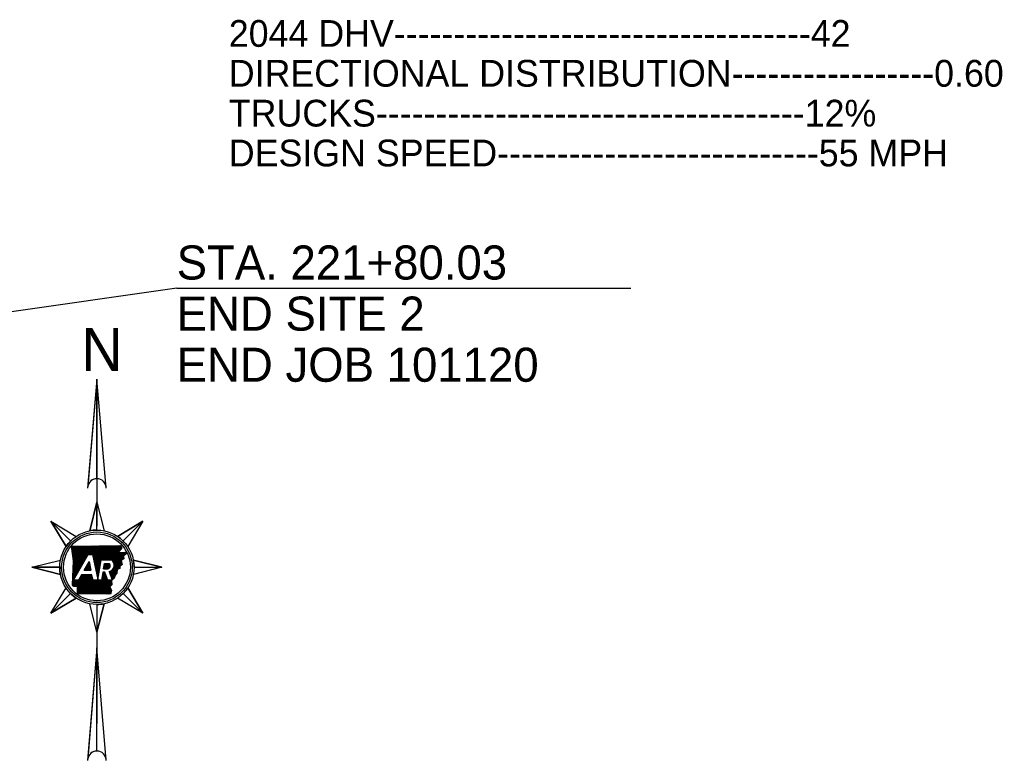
# Model space of a CAD drawing. Extents: x 1334737.7 to 1334827.2, y 402732.3 to 402753.5.
# Drawn here: x 1334760.94 to 1334768.55, y 402736.95 to 402742.69 of the extents above; entities that cross this region are included whole.
import ezdxf

# ---------------------------------------------------------------- set-up
doc = ezdxf.new("R2010")
doc.units = 0
for name, color, linetype in [('Default', 7, 'Continuous'), ('R_Dimension', 7, 'Continuous'), ('R_Draft', 7, 'Continuous')]:
    doc.layers.add(name, color=color, linetype=linetype)

msp = doc.modelspace()

# ---------------------------------------------------------------- linework, layer by layer
at = {"layer": 'Default'}
for q in [(1334753.3159, 402739.3518), (1334765.6746, 402740.6083)]:
    msp.add_line((1334762.1527, 402740.6083), q, dxfattribs=at)
at = {"layer": 'R_Dimension'}
for p, q in [((1334761.3382, 402738.6091), (1334761.3407, 402738.6116)), ((1334761.3391, 402738.6018), (1334761.3489, 402738.6116)), ((1334761.34, 402738.5946), (1334761.357, 402738.6116)), ((1334761.3409, 402738.5874), (1334761.3651, 402738.6116)), ((1334761.3418, 402738.5801), (1334761.3733, 402738.6116)), ((1334761.3427, 402738.5729), (1334761.3814, 402738.6116)), ((1334761.3436, 402738.5656), (1334761.3896, 402738.6116)), ((1334761.3445, 402738.5584), (1334761.3977, 402738.6116)), ((1334761.3454, 402738.5511), (1334761.4058, 402738.6116)), ((1334761.3463, 402738.5439), (1334761.414, 402738.6116)), ((1334761.3472, 402738.5366), (1334761.4221, 402738.6116)), ((1334761.3481, 402738.5294), (1334761.4303, 402738.6116)), ((1334761.349, 402738.5222), (1334761.4384, 402738.6116)), ((1334761.3499, 402738.5149), (1334761.4466, 402738.6116)), ((1334761.3502, 402738.4337), (1334761.5282, 402738.6117)), ((1334761.3505, 402738.4421), (1334761.52, 402738.6117)), ((1334761.3507, 402738.4506), (1334761.5119, 402738.6117)), ((1334761.3508, 402738.5077), (1334761.4547, 402738.6116)), ((1334761.351, 402738.459), (1334761.5037, 402738.6117)), ((1334761.3513, 402738.4674), (1334761.4955, 402738.6117)), ((1334761.3516, 402738.4758), (1334761.4874, 402738.6116)), ((1334761.3517, 402738.5004), (1334761.4629, 402738.6116)), ((1334761.3519, 402738.4843), (1334761.4792, 402738.6116)), ((1334761.3521, 402738.4927), (1334761.471, 402738.6116)), ((1334761.4712, 402738.5465), (1334761.5364, 402738.6117)), ((1334761.4793, 402738.5465), (1334761.5445, 402738.6118)), ((1334761.4875, 402738.5465), (1334761.5527, 402738.6118)), ((1334761.4956, 402738.5465), (1334761.561, 402738.612)), ((1334761.5007, 402738.5435), (1334761.5693, 402738.6121)), ((1334761.5021, 402738.5368), (1334761.5776, 402738.6122)), ((1334761.5035, 402738.5301), (1334761.5858, 402738.6123)), ((1334761.505, 402738.5233), (1334761.5941, 402738.6125)), ((1334761.5064, 402738.5166), (1334761.6024, 402738.6126)), ((1334761.5079, 402738.5099), (1334761.6107, 402738.6127)), ((1334761.5093, 402738.5032), (1334761.6189, 402738.6129)), ((1334761.5107, 402738.4965), (1334761.6272, 402738.613)), ((1334761.5122, 402738.4898), (1334761.6355, 402738.6131)), ((1334761.5136, 402738.4831), (1334761.6438, 402738.6132)), ((1334761.515, 402738.4764), (1334761.652, 402738.6134)), ((1334761.5165, 402738.4697), (1334761.6603, 402738.6135)), ((1334761.5179, 402738.4629), (1334761.6686, 402738.6137)), ((1334761.5193, 402738.4562), (1334761.677, 402738.6139)), ((1334761.5759, 402738.5047), (1334761.6853, 402738.614)), ((1334761.5841, 402738.5047), (1334761.6936, 402738.6142)), ((1334761.5922, 402738.5047), (1334761.702, 402738.6144)), ((1334761.6004, 402738.5047), (1334761.7103, 402738.6146)), ((1334761.6085, 402738.5047), (1334761.7187, 402738.6148)), ((1334761.6167, 402738.5047), (1334761.7205, 402738.6085)), ((1334761.6248, 402738.5047), (1334761.7244, 402738.6043)), ((1334761.633, 402738.5047), (1334761.7255, 402738.5972)), ((1334761.3496, 402738.4169), (1334761.4492, 402738.5164)), ((1334761.3499, 402738.4253), (1334761.4598, 402738.5352)), ((1334761.6411, 402738.5047), (1334761.7069, 402738.5704)), ((1334761.6485, 402738.5039), (1334761.7053, 402738.5607)), ((1334761.653, 402738.5002), (1334761.7139, 402738.5611)), ((1334761.6569, 402738.4961), (1334761.7224, 402738.5616)), ((1334761.6605, 402738.4914), (1334761.731, 402738.562)), ((1334761.6635, 402738.4863), (1334761.7396, 402738.5624)), ((1334761.666, 402738.4807), (1334761.7482, 402738.5629)), ((1334761.6673, 402738.4494), (1334761.7412, 402738.5233)), ((1334761.6679, 402738.4744), (1334761.7559, 402738.5625)), ((1334761.669, 402738.4673), (1334761.7598, 402738.5581)), ((1334761.669, 402738.4592), (1334761.7403, 402738.5305)), ((1334761.7321, 402738.5061), (1334761.7422, 402738.5161)), ((1334761.7561, 402738.5464), (1334761.7636, 402738.5538)), ((1334761.3485, 402738.3831), (1334761.4067, 402738.4413)), ((1334761.3488, 402738.3916), (1334761.4173, 402738.4601)), ((1334761.3491, 402738.4), (1334761.4279, 402738.4789)), ((1334761.3493, 402738.4084), (1334761.4386, 402738.4977)), ((1334761.4366, 402738.4246), (1334761.4785, 402738.4665)), ((1334761.4447, 402738.4246), (1334761.4799, 402738.4598)), ((1334761.4463, 402738.4425), (1334761.477, 402738.4732)), ((1334761.4529, 402738.4246), (1334761.4813, 402738.4531)), ((1334761.457, 402738.4613), (1334761.4756, 402738.4799)), ((1334761.461, 402738.4246), (1334761.4828, 402738.4464)), ((1334761.4676, 402738.4801), (1334761.4742, 402738.4866)), ((1334761.4692, 402738.4246), (1334761.4842, 402738.4396)), ((1334761.4773, 402738.4246), (1334761.4856, 402738.4329)), ((1334761.5208, 402738.4495), (1334761.567, 402738.4958)), ((1334761.5222, 402738.4428), (1334761.5653, 402738.4859)), ((1334761.5237, 402738.4361), (1334761.5636, 402738.476)), ((1334761.5251, 402738.4294), (1334761.5619, 402738.4662)), ((1334761.5265, 402738.4227), (1334761.5601, 402738.4563)), ((1334761.528, 402738.416), (1334761.5584, 402738.4464)), ((1334761.5294, 402738.4093), (1334761.5567, 402738.4366)), ((1334761.5857, 402738.4335), (1334761.6286, 402738.4764)), ((1334761.5874, 402738.4433), (1334761.6205, 402738.4764)), ((1334761.5891, 402738.4532), (1334761.6123, 402738.4764)), ((1334761.5908, 402738.463), (1334761.6042, 402738.4764)), ((1334761.5926, 402738.4729), (1334761.596, 402738.4764)), ((1334761.5939, 402738.4335), (1334761.6331, 402738.4727)), ((1334761.602, 402738.4335), (1334761.6359, 402738.4673)), ((1334761.6102, 402738.4335), (1334761.6374, 402738.4607)), ((1334761.6183, 402738.4335), (1334761.6367, 402738.4519)), ((1334761.6337, 402738.3995), (1334761.724, 402738.4898)), ((1334761.6359, 402738.3935), (1334761.7255, 402738.4832)), ((1334761.6381, 402738.3876), (1334761.727, 402738.4765)), ((1334761.6403, 402738.3816), (1334761.7286, 402738.4699)), ((1334761.6602, 402738.4342), (1334761.7225, 402738.4964)), ((1334761.7007, 402738.4339), (1334761.7121, 402738.4453)), ((1334761.3474, 402738.3494), (1334761.3641, 402738.3662)), ((1334761.3477, 402738.3579), (1334761.3747, 402738.385)), ((1334761.3479, 402738.3663), (1334761.3854, 402738.4037)), ((1334761.3482, 402738.3747), (1334761.396, 402738.4225)), ((1334761.3491, 402738.3023), (1334761.4348, 402738.388)), ((1334761.354, 402738.299), (1334761.4429, 402738.388)), ((1334761.3598, 402738.2967), (1334761.4511, 402738.388)), ((1334761.3695, 402738.2983), (1334761.4592, 402738.388)), ((1334761.3778, 402738.2984), (1334761.4674, 402738.388)), ((1334761.3842, 402738.2966), (1334761.4755, 402738.388)), ((1334761.3844, 402738.2887), (1334761.4837, 402738.388)), ((1334761.3845, 402738.2806), (1334761.4918, 402738.388)), ((1334761.3845, 402738.2725), (1334761.4961, 402738.3841)), ((1334761.3845, 402738.2644), (1334761.4975, 402738.3774)), ((1334761.3845, 402738.2562), (1334761.499, 402738.3707)), ((1334761.3845, 402738.2481), (1334761.5004, 402738.364)), ((1334761.3847, 402738.2401), (1334761.5018, 402738.3573)), ((1334761.4008, 402738.3622), (1334761.4266, 402738.388)), ((1334761.4115, 402738.3809), (1334761.4185, 402738.388)), ((1334761.466, 402738.24), (1334761.6062, 402738.3801)), ((1334761.4742, 402738.24), (1334761.6083, 402738.3741)), ((1334761.4823, 402738.2399), (1334761.6105, 402738.3682)), ((1334761.4855, 402738.4246), (1334761.4871, 402738.4262)), ((1334761.4904, 402738.2399), (1334761.6127, 402738.3622)), ((1334761.4986, 402738.2399), (1334761.6149, 402738.3563)), ((1334761.5308, 402738.4025), (1334761.555, 402738.4267)), ((1334761.5323, 402738.3958), (1334761.5533, 402738.4168)), ((1334761.5337, 402738.3891), (1334761.5515, 402738.4069)), ((1334761.5351, 402738.3824), (1334761.5498, 402738.3971)), ((1334761.5366, 402738.3757), (1334761.5481, 402738.3872)), ((1334761.538, 402738.369), (1334761.5464, 402738.3773)), ((1334761.5395, 402738.3623), (1334761.5447, 402738.3675)), ((1334761.5409, 402738.3556), (1334761.5429, 402738.3576)), ((1334761.5718, 402738.3539), (1334761.604, 402738.386)), ((1334761.5736, 402738.3638), (1334761.6018, 402738.392)), ((1334761.5753, 402738.3737), (1334761.5996, 402738.3979)), ((1334761.577, 402738.3835), (1334761.5974, 402738.4039)), ((1334761.5787, 402738.3934), (1334761.595, 402738.4097)), ((1334761.5804, 402738.4033), (1334761.5868, 402738.4097)), ((1334761.6293, 402738.4114), (1334761.6317, 402738.4138)), ((1334761.6315, 402738.4054), (1334761.647, 402738.4209)), ((1334761.6425, 402738.3757), (1334761.6913, 402738.4245)), ((1334761.6447, 402738.3697), (1334761.6904, 402738.4155)), ((1334761.6469, 402738.3638), (1334761.6895, 402738.4064)), ((1334761.6491, 402738.3578), (1334761.674, 402738.3828)), ((1334761.6512, 402738.3519), (1334761.6705, 402738.3712)), ((1334761.3461, 402738.3074), (1334761.3845, 402738.3458)), ((1334761.3463, 402738.3157), (1334761.3764, 402738.3458)), ((1334761.3465, 402738.3242), (1334761.3682, 402738.3458)), ((1334761.3468, 402738.3326), (1334761.3601, 402738.3458)), ((1334761.3471, 402738.341), (1334761.3535, 402738.3474)), ((1334761.3928, 402738.2401), (1334761.5033, 402738.3505)), ((1334761.401, 402738.2401), (1334761.5067, 402738.3458)), ((1334761.4091, 402738.2401), (1334761.5149, 402738.3458)), ((1334761.4172, 402738.24), (1334761.523, 402738.3458)), ((1334761.4254, 402738.24), (1334761.5312, 402738.3458)), ((1334761.4335, 402738.24), (1334761.5393, 402738.3458)), ((1334761.4416, 402738.24), (1334761.5475, 402738.3458)), ((1334761.4498, 402738.24), (1334761.5556, 402738.3458)), ((1334761.4579, 402738.24), (1334761.5637, 402738.3458)), ((1334761.5067, 402738.2399), (1334761.6171, 402738.3503)), ((1334761.5148, 402738.2399), (1334761.6208, 402738.3458)), ((1334761.523, 402738.2399), (1334761.6289, 402738.3458)), ((1334761.5311, 402738.2399), (1334761.6371, 402738.3458)), ((1334761.5392, 402738.2398), (1334761.6452, 402738.3458)), ((1334761.5474, 402738.2398), (1334761.6479, 402738.3404)), ((1334761.5555, 402738.2398), (1334761.6483, 402738.3326)), ((1334761.5636, 402738.2398), (1334761.6487, 402738.3249)), ((1334761.5718, 402738.2398), (1334761.649, 402738.3171)), ((1334761.5799, 402738.2398), (1334761.6357, 402738.2955)), ((1334761.588, 402738.2398), (1334761.6382, 402738.2899)), ((1334761.5962, 402738.2398), (1334761.6407, 402738.2843)), ((1334761.6043, 402738.2397), (1334761.6432, 402738.2786)), ((1334761.6124, 402738.2397), (1334761.6457, 402738.273)), ((1334761.6206, 402738.2397), (1334761.6478, 402738.267)), ((1334761.6287, 402738.2397), (1334761.6441, 402738.2551)), ((1334761.6368, 402738.2397), (1334761.6405, 402738.2433))]:
    msp.add_line(p, q, dxfattribs=at)
msp.add_circle((1334761.5345, 402738.4467), 0.2736, dxfattribs=at)
at = {"layer": 'R_Draft'}
for p, q in [((1334761.5345, 402739.9034), (1334761.4635, 402739.0731)), ((1334761.5345, 402739.9034), (1334761.5345, 402738.7662)), ((1334761.5345, 402739.1329), (1334761.5345, 402739.9034)), ((1334761.4645, 402739.0847), (1334761.4678, 402739.0879)), ((1334761.4649, 402739.0891), (1334761.4715, 402739.0957)), ((1334761.5345, 402738.9508), (1334761.4784, 402738.7293)), ((1334761.5345, 402738.7348), (1334761.5345, 402738.9508)), ((1334761.1781, 402738.8032), (1334761.3308, 402738.6504)), ((1334761.3308, 402738.6504), (1334761.1781, 402738.8032)), ((1334761.1781, 402738.8032), (1334761.2951, 402738.6069)), ((1334761.891, 402738.8032), (1334761.6946, 402738.6862)), ((1334761.7382, 402738.6504), (1334761.891, 402738.8032)), ((1334761.7382, 402738.6504), (1334761.891, 402738.8032)), ((1334761.3526, 402738.3458), (1334761.4662, 402738.5465)), ((1334761.4662, 402738.5465), (1334761.5, 402738.5465)), ((1334761.5686, 402738.5047), (1334761.6475, 402738.5047)), ((1334761.0304, 402738.4467), (1334761.2465, 402738.4467)), ((1334761.2465, 402738.4467), (1334761.0304, 402738.4467)), ((1334761.0304, 402738.4467), (1334761.252, 402738.3906)), ((1334761.4362, 402738.4246), (1334761.4734, 402738.4903)), ((1334761.5857, 402738.4335), (1334761.6195, 402738.4335)), ((1334761.5932, 402738.4764), (1334761.6302, 402738.4764)), ((1334762.0386, 402738.4467), (1334761.817, 402738.5028)), ((1334761.8226, 402738.4467), (1334762.0386, 402738.4467)), ((1334761.8226, 402738.4467), (1334762.0386, 402738.4467)), ((1334761.4154, 402738.388), (1334761.3916, 402738.3458)), ((1334761.4953, 402738.388), (1334761.4154, 402738.388)), ((1334761.4362, 402738.4246), (1334761.4874, 402738.4246)), ((1334761.5952, 402738.4097), (1334761.5815, 402738.4097)), ((1334761.6188, 402738.3458), (1334761.5952, 402738.4097)), ((1334761.6286, 402738.4131), (1334761.6535, 402738.3458)), ((1334761.3916, 402738.3458), (1334761.3526, 402738.3458)), ((1334761.5704, 402738.3458), (1334761.5043, 402738.3458)), ((1334761.6535, 402738.3458), (1334761.6188, 402738.3458)), ((1334761.891, 402738.0903), (1334761.774, 402738.2866)), ((1334761.1781, 402738.0903), (1334761.3308, 402738.2431)), ((1334761.3308, 402738.2431), (1334761.1781, 402738.0903)), ((1334761.1781, 402738.0903), (1334761.3744, 402738.2073)), ((1334761.7382, 402738.2431), (1334761.891, 402738.0903)), ((1334761.7382, 402738.2431), (1334761.891, 402738.0903)), ((1334761.5345, 402737.9427), (1334761.5906, 402738.1642)), ((1334761.5345, 402738.1587), (1334761.5345, 402738.1587)), ((1334761.5345, 402738.1587), (1334761.5345, 402737.2366)), ((1334761.5345, 402738.1587), (1334761.5345, 402737.9427)), ((1334761.5345, 402737.8223), (1334761.4635, 402736.9627)), ((1334761.5345, 402737.0229), (1334761.5345, 402737.8223))]:
    msp.add_line(p, q, dxfattribs=at)
for points in [[(1334761.6065, 402739.0609), (1334761.5345, 402739.9034), (1334761.4625, 402739.0609)], [(1334761.4784, 402738.7293), (1334761.5345, 402738.9508), (1334761.5906, 402738.7293)], [(1334761.2951, 402738.6069), (1334761.1781, 402738.8032), (1334761.3744, 402738.6862)], [(1334761.6946, 402738.6862), (1334761.891, 402738.8032), (1334761.774, 402738.6069)], [(1334761.3379, 402738.6116), (1334761.4503, 402738.6116), (1334761.5489, 402738.6118), (1334761.6653, 402738.6136), (1334761.7192, 402738.6148)], [(1334761.346, 402738.3075), (1334761.3522, 402738.4961), (1334761.3379, 402738.6116)], [(1334761.5, 402738.5465), (1334761.5418, 402738.3512), (1334761.5686, 402738.5047)], [(1334761.7545, 402738.5632), (1334761.7642, 402738.553), (1334761.74, 402738.5331), (1334761.7426, 402738.513), (1334761.7218, 402738.4993), (1334761.7289, 402738.4683), (1334761.7129, 402738.4537), (1334761.7115, 402738.4378), (1334761.692, 402738.4308), (1334761.6889, 402738.4008), (1334761.6749, 402738.3858), (1334761.6682, 402738.3632), (1334761.6478, 402738.3445), (1334761.6493, 402738.3116), (1334761.6354, 402738.296), (1334761.6481, 402738.2678), (1334761.6393, 402738.2397)], [(1334761.7025, 402738.5605), (1334761.7553, 402738.5633)], [(1334761.252, 402738.3906), (1334761.0304, 402738.4467), (1334761.252, 402738.5028)], [(1334761.4734, 402738.4903), (1334761.4874, 402738.4246)], [(1334761.5857, 402738.4335), (1334761.5932, 402738.4764)], [(1334761.817, 402738.5028), (1334762.0386, 402738.4467), (1334761.817, 402738.3906)], [(1334761.5043, 402738.3458), (1334761.4953, 402738.388)], [(1334761.5815, 402738.4097), (1334761.5704, 402738.3458)], [(1334761.3744, 402738.2073), (1334761.1781, 402738.0903), (1334761.2951, 402738.2866)], [(1334761.6393, 402738.2397), (1334761.3846, 402738.2401), (1334761.3844, 402738.2963)], [(1334761.774, 402738.2866), (1334761.891, 402738.0903), (1334761.6946, 402738.2073)], [(1334761.5906, 402738.1642), (1334761.5345, 402737.9427), (1334761.4784, 402738.1642)], [(1334761.6065, 402736.9509), (1334761.5345, 402737.8223), (1334761.4625, 402736.9509)]]:
    msp.add_lwpolyline(points, dxfattribs=at)
for radius in [0.288, 0.2592]:
    msp.add_circle((1334761.5345, 402738.4467), radius, dxfattribs=at)
for centre, radius, start, end in [((1334761.5345, 402739.0609), 0.072, 0, 180), ((1334761.5345, 402739.0609), 0.072, 90, 170.22959), ((1334761.5345, 402738.4467), 0.288, 90, 101.22909), ((1334761.5345, 402738.4467), 0.288, 45, 56.22909), ((1334761.5345, 402738.4467), 0.288, 135, 146.22909), ((1334761.6182, 402738.463), 0.051, 281.86262, 54.87052), ((1334761.5345, 402738.4467), 0.288, 180, 191.22909), ((1334761.6114, 402738.4583), 0.0261, 288.12683, 43.89016), ((1334761.5345, 402738.4467), 0.288, 0, 11.22909), ((1334761.5345, 402738.4467), 0.288, 315, 326.22909), ((1334761.5345, 402738.4467), 0.288, 225, 236.22909), ((1334761.5345, 402738.4467), 0.288, 270, 281.22909), ((1334761.5345, 402736.9509), 0.072, 0, 180), ((1334761.5345, 402736.9509), 0.072, 90, 170.5511)]:
    msp.add_arc(centre, radius, start, end, dxfattribs=at)
for points in [[(1334761.7192, 402738.6148), (1334761.7195, 402738.6118), (1334761.7205, 402738.6102), (1334761.7207, 402738.6073), (1334761.7218, 402738.606), (1334761.7238, 402738.6048), (1334761.7257, 402738.6027), (1334761.7261, 402738.6004), (1334761.7255, 402738.5979), (1334761.7254, 402738.5952), (1334761.7251, 402738.5929), (1334761.7247, 402738.5907), (1334761.723, 402738.589), (1334761.7214, 402738.5877), (1334761.72, 402738.5863), (1334761.7189, 402738.5847), (1334761.7171, 402738.5831), (1334761.7153, 402738.5813), (1334761.7138, 402738.5798), (1334761.7124, 402738.5779), (1334761.7117, 402738.5757), (1334761.7101, 402738.5742), (1334761.7088, 402738.5728), (1334761.7072, 402738.5709), (1334761.7063, 402738.569), (1334761.7047, 402738.5669), (1334761.7044, 402738.5648), (1334761.7033, 402738.5631), (1334761.7033, 402738.5628)], [(1334761.3844, 402738.2963), (1334761.3847, 402738.2962), (1334761.3834, 402738.2971), (1334761.3816, 402738.298), (1334761.3796, 402738.2981), (1334761.377, 402738.2985), (1334761.3748, 402738.2987), (1334761.3726, 402738.3002), (1334761.3702, 402738.2986), (1334761.3676, 402738.2975), (1334761.3661, 402738.2988), (1334761.3641, 402738.2979), (1334761.3627, 402738.2983), (1334761.3602, 402738.2967), (1334761.3579, 402738.2973), (1334761.3563, 402738.2968), (1334761.3542, 402738.2969), (1334761.3538, 402738.2993), (1334761.3518, 402738.2996), (1334761.35, 402738.3006), (1334761.3488, 402738.303), (1334761.348, 402738.3049), (1334761.346, 402738.3075)]]:
    msp.add_spline(points, degree=3, dxfattribs=at)

# ---------------------------------------------------------------- texts
at = {"layer": 'Default'}
for s, height, p in [('2044 DHV-----------------------------------42', 0.207393, (1334762.5569, 402742.4793)), ('DIRECTIONAL DISTRIBUTION-----------------0.60', 0.207393, (1334762.5569, 402742.1705)), ('TRUCKS------------------------------------12%', 0.207393, (1334762.5569, 402741.8617)), ('DESIGN SPEED---------------------------55 MPH', 0.207393, (1334762.5569, 402741.5529)), ('STA. 221+80.03', 0.264042, (1334762.1527, 402740.6763)), ('END SITE 2', 0.26404, (1334762.1527, 402740.2802)), ('END JOB 101120', 0.264042, (1334762.1527, 402739.8842))]:
    msp.add_text(s, height=height, dxfattribs=at).set_placement(p)
at = {"layer": 'R_Draft'}
for s, height, p in [('N', 0.3324, (1334761.4131, 402739.9688)), ('DWB 7-27-17', 0.005601, (1334761.5169, 402738.1827))]:
    msp.add_text(s, height=height, dxfattribs=at).set_placement(p)

doc.saveas('drawing.dxf')
